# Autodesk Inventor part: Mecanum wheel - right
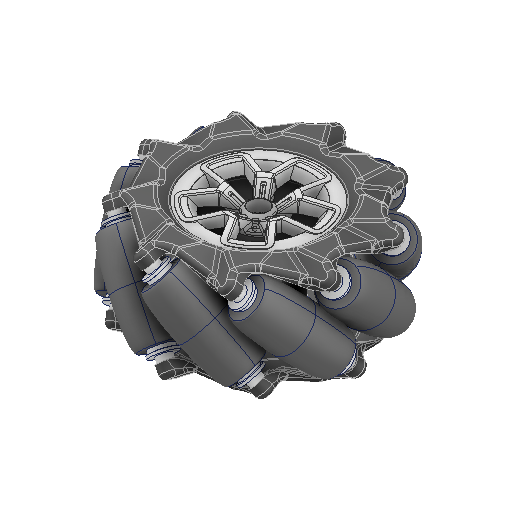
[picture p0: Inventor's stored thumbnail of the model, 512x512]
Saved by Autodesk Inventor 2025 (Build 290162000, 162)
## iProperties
Created: 2024-11
Part Number: Mecanum wheel - right
Material: Generico
Description: STEP AP214
Document SubType Name: Modeling
Designer: R5800u
Density: 1 g/cm^3
Appearance: Default
Sending System: SolidWorks 2022
Preprocessor: SwSTEP 2.0
Title: Mecanum wheel - right.STEP
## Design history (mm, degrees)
feature "Половина колеса Mecanum_Верхняя половина - правая_1:1"
feature "Половина колеса Mecanum_Нижняя половина - правая_2:1"
feature "Декоративная накладка_3:1"
feature "Ролик колеса Mecanum_4:1"
feature "Ролик колеса Mecanum_5:1"
feature "Ролик колеса Mecanum_6:1"
feature "Ролик колеса Mecanum_7:1"
feature "Ролик колеса Mecanum_8:1"
feature "Ролик колеса Mecanum_9:1"
feature "Ролик колеса Mecanum_10:1"
feature "Ролик колеса Mecanum_11:1"
feature "Ролик колеса Mecanum_12:1"
node "Solido1"
node "Solido2"
node "Solido3"
node "Solido4"
node "Solido5"
node "Solido6"
node "Solido7"
node "Solido8"
node "Solido9"
node "Solido10"
node "Solido11"
node "Solido12"
